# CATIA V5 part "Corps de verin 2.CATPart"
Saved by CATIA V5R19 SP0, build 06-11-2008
Part number: Corps de verin 2
Bounding box of the stored display mesh (mm): x -24.59 to 83.41, y -11.997 to 11.997, z -11.864 to 11.864
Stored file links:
  G:\EU_thinkMotion\CFAO_2010\St2M_groupe2\St2M_groupe2\csayed\csayed\csayed\Corps de verin 2.CATPart
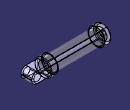
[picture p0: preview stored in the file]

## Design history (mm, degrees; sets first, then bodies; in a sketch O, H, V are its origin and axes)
Body1 (main body)
  Sketch1 on zx-plane, origin (0, 0, 0), H (-1, 0, 0), V (0, 0, 1)
    line L1 (-60.4097, 0) -> (-60.4097, 12)
    point P1 (-60.4097, 0)
    line L2 (-60.4097, 12) -> (-50.4097, 12)
    line L3 (-50.4097, 12) -> (-50.4097, 10)
    line L4 (-50.4097, 10) -> (14.5903, 10)
    line L5 (14.5903, 10) -> (14.5903, 12)
    line L6 (14.5903, 12) -> (24.5903, 12)
    line L7 (-58.4097, 0) -> (-58.4097, 8)
    point P8 (-58.4097, 0)
    line L8 (-58.4097, 8) -> (21.59, 8)
    line L9 (24.5903, 12) -> (24.5903, 3)
    line L10 (24.5903, 3) -> (21.5903, 3)
    line L11 (21.59, 8) -> (21.5903, 3)
    distance L1 L7 = 2
    coincidence: P1 H, P8 H
    vertical: L1 V, L3 V, L5 V, L7 V, L9 V
    horizontal: L2 H, L4 H, L6 H, L8 H, L10 H
  Shaft1: profile Sketch1, axis Sketch1.H, angle 360
  Sketch2 on face of Shaft1 from Sketch1.L1, origin (60.4097, 0, 0), H (0, 1, 0), V (0, 0, 1)
    line L1 (-7.5, 7.5) -> (7.5, 7.5)
    line L2 (7.5, 7.5) -> (7.5, -7.5)
    line L3 (7.5, -7.5) -> (-7.5, -7.5)
    line L4 (-7.5, -7.5) -> (-7.5, 7.5)
    horizontal: L1 H, L3 H
    vertical: L2 V, L4 V
  Pad1: profile Sketch2, direction (1, 0, 0), length 23
  Fillet1: radius 7, on edge [face of Pad1 from Sketch2.L3 | end face of Pad1]; edge [face of Pad1 from Sketch2.L1 | end face of Pad1]
  Sketch3 on face of Pad1 from Sketch2.L2, origin (0, 7.5, 0), H (-1, 0, 0), V (0, 0, 1)
    circle A1 centre (-75.6986, 0) radius 5
    point P1 (-75.6986, 0)
    point P2 (-70.6986, 0)
    reference projected line E1 through (0, 0) direction (1, 0) from axis of face of Shaft1 from Sketch1.L4
    distance P1 E1 = 0
    coincidence: A1 P2, P2 H
  Pocket1: profile Sketch3, direction (0, -1, 0), through (limit type 3)
  Fillet2: radius 1, on edge [face of Shaft1 from Sketch1.L1 | face of Shaft1 from Sketch1.L2]
  Chamfer1: length 1, angle 45, on edge [face of Shaft1 from Sketch1.L4 | face of Shaft1 from Sketch1.L5]
  Chamfer2: length 1, angle 45, on edge [face of Shaft1 from Sketch1.L3 | face of Shaft1 from Sketch1.L4]
  Fillet3: radius 2, on edge [face of Shaft1 from Sketch1.L6 | face of Shaft1 from Sketch1.L9]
